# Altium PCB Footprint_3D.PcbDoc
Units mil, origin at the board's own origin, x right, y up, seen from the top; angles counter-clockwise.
Board outline 6000 x 4000 mil, 2 copper layers (Top Layer, Bottom Layer); 1 components, 0 nets, 42 pads, 0 vias.
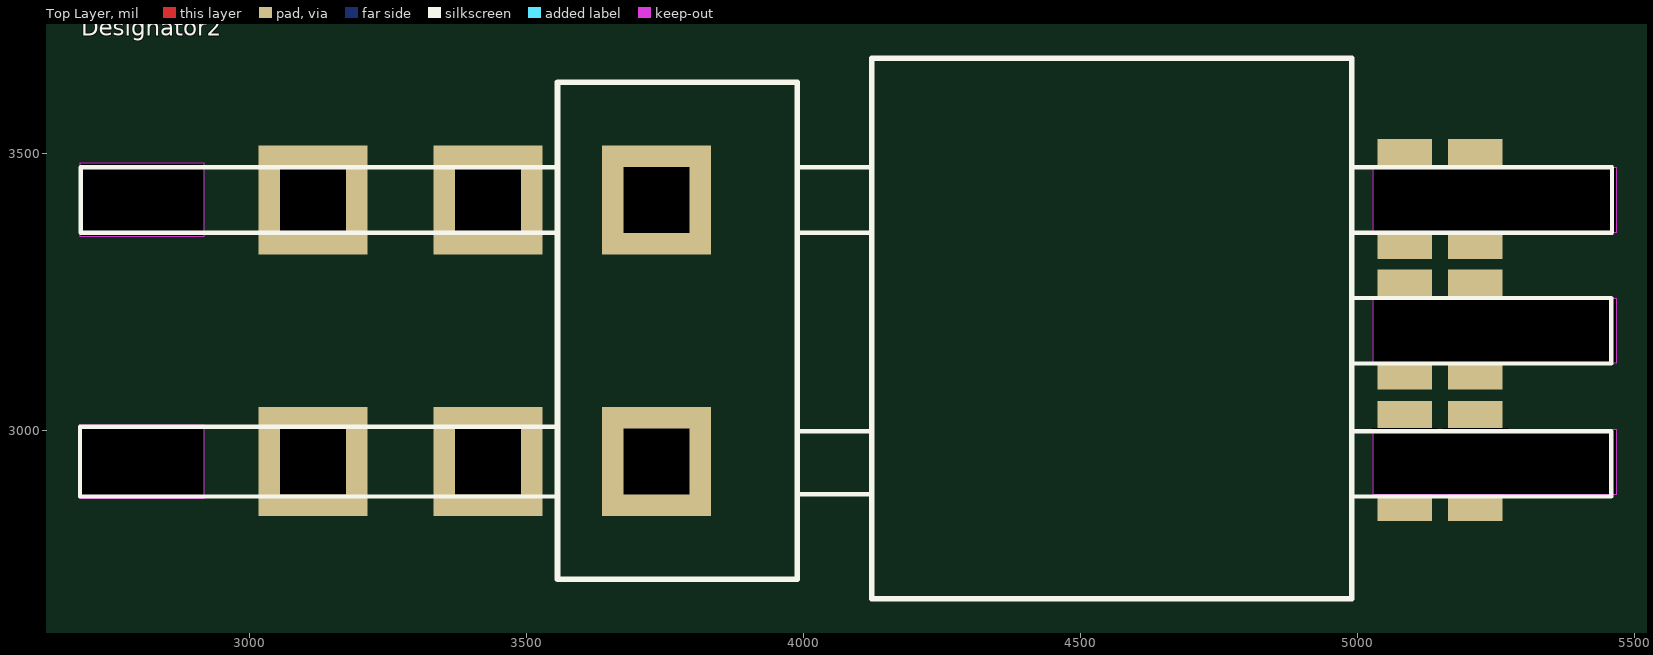
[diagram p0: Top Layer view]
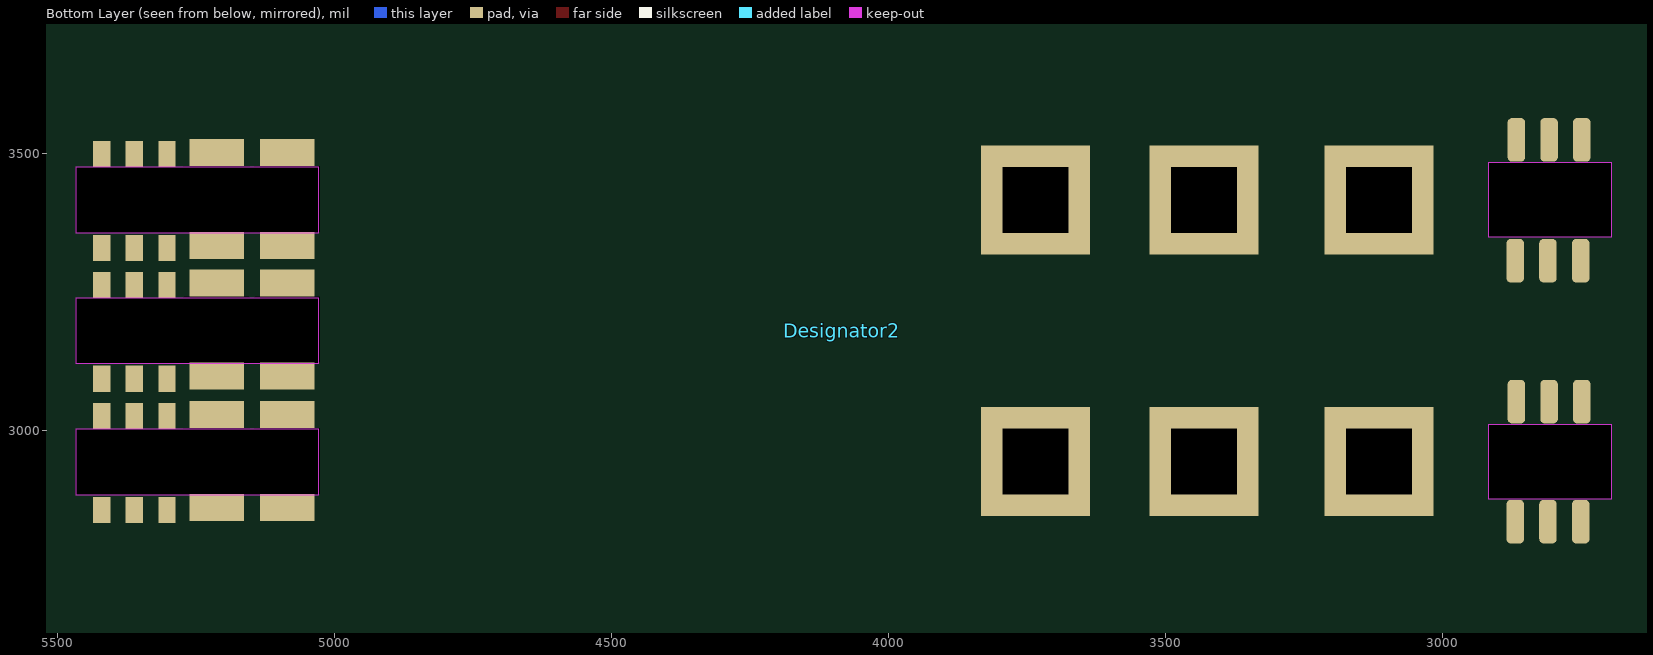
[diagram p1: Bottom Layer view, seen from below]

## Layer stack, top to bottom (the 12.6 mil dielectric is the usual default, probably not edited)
Top Solder: solder mask 0.4, Solder Resist, Dk 3.5
Top Layer: signal copper 1.4
Dielectric 1: dielectric 12.6, FR-4, Dk 4.8
Bottom Layer: signal copper 1.4
Bottom Solder: solder mask 0.4, Solder Resist, Dk 3.5

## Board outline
1000,1000 7000,1000 7000,5000 1000,5000

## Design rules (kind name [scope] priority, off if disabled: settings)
Clearance Clearance_1 [OnMid vs OnMid] p1: gap=10 ignorepadtopadclearanceinfootprint=FALSE sourcerule=36 cellrowname=All cellrowtype=0 cellcolname=All cellcoltype=0 innerlayers=TRUE
Clearance Clearance_2 [(ExistsOnLayer('Top Layer') Or ExistsOnLayer('Bottom Layer')) vs (ExistsOnLayer('Top Layer') Or ExistsOnLayer('Bottom Layer'))] p2: gap=10 ignorepadtopadclearanceinfootprint=FALSE sourcerule=36 cellrowname=All cellrowtype=0 cellcolname=All cellcoltype=0 outerlayers=TRUE
Clearance [All] p3: gap=10 ignorepadtopadclearanceinfootprint=FALSE ismatrix=TRUE
Height [All] p1: minheight=0 maxheight=1299.21 prefheight=500
PolygonConnect [All] p1: connectstyle=Relief reliefconductorwidth=10 reliefentries=4 polygonreliefangle="90 Angle" airgapwidth=10
RoutingVias [All] p1: holewidth=28 width=50 viastyle="Through Hole" minholewidth=28 minwidth=50 maxholewidth=28 maxwidth=50
SolderMaskExpansion [All] p1: expansion=4 istentingtop=FALSE
Width [All] p1: maxlimit=10 minlimit=10 preferedwidth=10
29 further rules are at their usual default settings.

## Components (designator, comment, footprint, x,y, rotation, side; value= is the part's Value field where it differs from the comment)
Designator2 "Comment" XFMR-PMP41114 4085,3180 r0 top

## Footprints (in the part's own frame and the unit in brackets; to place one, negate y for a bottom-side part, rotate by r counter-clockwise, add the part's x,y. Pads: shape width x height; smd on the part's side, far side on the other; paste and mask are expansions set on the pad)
XFMR-PMP41114 [mm]
  rrect50% 0.8x2 smd far side: P1a(-33.874,-8.75) P1b(-33.874,3.21) P2a(-33.925,-3.25) P2b(-33.925,8.75) P3a(-32.374,-8.75) P3b(-32.374,3.21) P4a(-32.425,-3.25) P4b(-32.425,8.75) P5a(-30.874,-8.75) P5b(-30.874,3.21) P6a(-30.925,-3.25) P6b(-30.925,8.75)
  rect 5x5 hole 3 square: P7a(-24.623,-6.001) P7b(-24.622,5.999) P8a(-16.605,-6.001) P8b(-16.605,5.999) P9a(-8.876,-6.001) P9b(-8.875,5.999)
  rect 0.8x1.2 smd far side: S1(33.925,-8.212) S1(33.925,-2.201) S1(33.925,3.799) S2(33.925,-3.912) S2(33.925,2.099) S2(33.925,8.099) S3(32.425,-8.212) S3(32.425,-2.201) S3(32.425,3.799) S4(32.425,-3.912) S4(32.425,2.099) S4(32.425,8.099) S5(30.925,-8.212) S5(30.925,-2.201) S5(30.925,3.799) S6(30.925,-3.912) S6(30.925,2.099) S6(30.925,8.099)
  rect 2.5x5.5 hole 3 square: S7(28.654,-5.962) S7(28.654,0.049) S7(28.654,6.049) S8(25.414,-5.962) S8(25.414,0.049) S8(25.414,6.049)
  Keep-Out Layer board cut-out: 23.961,4.499 23.961,7.499 35.111,7.499 35.111,4.499
  Keep-Out Layer board cut-out: 23.961,-1.501 23.961,1.499 35.111,1.499 35.111,-1.501
  Keep-Out Layer board cut-out: -35.289,4.299 -35.289,7.699 -29.639,7.699 -29.639,4.299
  Keep-Out Layer board cut-out: 23.961,-7.511 23.961,-4.511 35.111,-4.511 35.111,-7.511
  Keep-Out Layer board cut-out: -35.289,-7.701 -35.289,-4.301 -29.639,-4.301 -29.639,-7.701
  silkscreen extent -35.31,-12.28 34.91,12.5, body extent -35.4,-11.68 34.9,12.4, height 32.13

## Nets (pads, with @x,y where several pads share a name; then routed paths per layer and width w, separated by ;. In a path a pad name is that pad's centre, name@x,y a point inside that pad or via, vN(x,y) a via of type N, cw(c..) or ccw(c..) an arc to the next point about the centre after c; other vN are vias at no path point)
pads on no net: Designator2.P1a Designator2.P1b Designator2.P2a Designator2.P2b Designator2.P3a Designator2.P3b Designator2.P4a Designator2.P4b Designator2.P5a Designator2.P5b Designator2.P6a Designator2.P6b Designator2.P7a Designator2.P7b Designator2.P8a Designator2.P8b Designator2.P9a Designator2.P9b Designator2.S1 Designator2.S2 Designator2.S3 Designator2.S4 Designator2.S5 Designator2.S6 Designator2.S7 Designator2.S8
